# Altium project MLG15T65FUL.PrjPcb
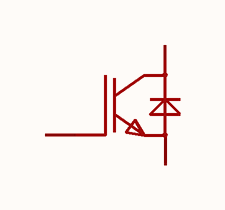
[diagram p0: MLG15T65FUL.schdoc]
1 sheet, 1 parts. Net scope: global (net labels, ports and power ports of the same name join across sheets).

## Sheet MLG15T65FUL.schdoc
size 127 x 101 mm

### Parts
Q?  mlg15t65ful  [TO-220-3_L10.0-W4.5-P2.54-L-1]  (value not drawn)

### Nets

Not connected (* = marked no-connect by the designer): Q? 1(G) 2(C) 3(E)

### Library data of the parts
Q? = mlg15t65ful: IGBT类型:FS(场截止);耗散功率(Pd):41W;集射极击穿电压(Vces):650V;集电极电流(Ic):15A;; Manufacturer: minos(迈诺斯); AddInBom: yes; ModelId: f3b81a431813461aaa6f5a84087f9609; ModelTransform: 393.7,177.5587,0,0,0,0,0,16.417,-196.85; Pd - Power Dissipation: 41W; Collector-Emitter Breakdown Voltage (Vces): 650V; Current - Collector(Ic): 15A; Current - Collector Pulsed (Icm): 60A; Vce Saturation(VCE(sat)): 1.8V@15A,15V; Gate-Emitter Threshold Voltage (Vge(th)@Ic): 5.8V@1mA; Gate Charge(Qg): 44nC@15V; Input Capacitance(Cies): 892pF; Output Capacitance(Coes): 43pF; Reverse Transfer Capacitance (Cres): 10pF; Td(on): 11ns; Td(off): 99ns; Turn-On Energy (Eon): 210uJ; Switching Energy(Eoff): 260uJ; Reverse Recovery Time(trr): 58ns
